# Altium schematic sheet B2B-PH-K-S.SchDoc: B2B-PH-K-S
size 296 x 210 mm; Revision: 1.0; DocumentSize: A4
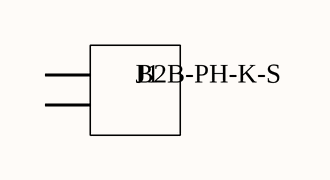
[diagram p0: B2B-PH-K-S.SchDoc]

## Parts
J1  value B2B-PH-K-S

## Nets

Not connected (* = marked no-connect by the designer): J1 1 2

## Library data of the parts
J1 = B2B-PH-K-S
